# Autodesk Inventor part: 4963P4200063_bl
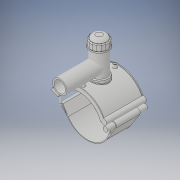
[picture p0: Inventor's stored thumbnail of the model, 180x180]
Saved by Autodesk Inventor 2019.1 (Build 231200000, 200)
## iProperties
Created: 2017-07
Part Number: 4963P4200063_bl
Material: Generic
Document SubType Name: Modeling
Designer: KIM
Density: 1 g/cm^3
Appearance: Default
Author: KIM
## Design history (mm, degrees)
derived "4963P4.ipt"
feature "Solid1::4963P4.ipt" dims "ScaleForDerivedMember" = 10
feature "Solid2::4963P4.ipt" dims "ScaleForDerivedMember" = 10
feature "Solid3::4963P4.ipt" dims "ScaleForDerivedMember" = 10
tag "TaggingFeature1"
body "Solid1"
body "Solid2"
body "Solid3"
other parameters: "d2" = 262.6 [user parameter], "d4" = 176 [user parameter], "d5" = 0 [user parameter], "d6" = 0.1 [user parameter], "d8" = 0 [user parameter], "d19" = 6 [user parameter], "d20" = 6 [user parameter], "d21" = 105.6 [user parameter], "d23" = 0 [user parameter], "d24" = 52.8 [user parameter], "d26" = 0 [user parameter], "d27" = 3 [user parameter], "d28" = 3 [user parameter], "d29" = 3 [user parameter], "d30" = 66.66667 [user parameter], "d31" = 6 [user parameter], "d32" = 0 [user parameter], "d33" = 0 [user parameter], "d34" = 0.6 [user parameter], "d40" = 120.64 [user parameter], "d43" = 0 [user parameter], "d45" = 0 [user parameter], "d47" = 221.6 [user parameter], "d70" = 15 [user parameter], "d72" = 0 [user parameter], "d73" = 6 [user parameter], "d75" = 5 [user parameter], "d76" = 0 [user parameter], "d79" = 15 [user parameter], "d80" = 70.4 [user parameter], "d82" = 5 deg [user parameter], "d84" = 4 [user parameter], "d85" = 14 [user parameter], "d86" = 0 [user parameter], "d87" = 3 [user parameter], "d88" = 0 [user parameter], "d89" = 1 [user parameter], "d90" = 1 [user parameter], "d91" = 140.8 [user parameter], "d92" = 0 [user parameter], "d93" = 0.5 [user parameter], "d94" = 105.26316 [user parameter], "d96" = 236.64 [user parameter], "d97" = 3.52 [user parameter], "d98" = 0 [user parameter], "d102" = 2 [user parameter], "d120" = 140 deg [user parameter], "d121" = 24.228 [user parameter], "d122" = 20 deg [user parameter], "d123" = 464 [user parameter], "d124" = 139.2 [user parameter], "d126" = 0 [user parameter], "d143" = 206 [user parameter], "d145" = 24.61538 [user parameter], "d149" = 3 [user parameter], "d150" = 27.07692 [user parameter], "d153" = 176 [user parameter], "d154" = 0 [user parameter], "d156" = 116 [user parameter], "d157" = 160 deg [user parameter], "d159" = 6.4 [user parameter], "d161" = 3 [user parameter], "d162" = 105.6 [user parameter], "d163" = 0 [user parameter], "d168" = 113.17073 [user parameter], "d170" = 3 [user parameter], "d172" = 0 [user parameter], "d173" = 1 [user parameter], "d176" = 20 deg [user parameter], "d177" = 14 [user parameter], "d178" = 32 [user parameter], "d180" = 0 [user parameter], "d183" = 12.8 [user parameter], "d184" = 11.2 [user parameter], "d185" = 57.2 [user parameter], "d186" = 57.2 [user parameter], "d187" = 116 [user parameter], "d188" = 9.6 [user parameter], "d189" = 14 [user parameter], "d190" = 0 [user parameter], "d191" = 174 [user parameter], "d193" = 6.4 [user parameter], "d194" = 6.16 [user parameter], "d195" = 90 deg [user parameter], "d197" = 0 [user parameter], "d199" = 0 [user parameter], "d200" = 16 [user parameter], "d202" = 0 [user parameter], "d203" = 177 [user parameter], "d204" = 76 [user parameter], "d205" = 56 [user parameter], "d206" = 68 [user parameter], "d207" = 132.75 [user parameter], "d208" = 138.06 [user parameter], "d209" = 164.61 [user parameter], "d210" = 68.8 [user parameter], "d212" = 64 [user parameter], "d213" = 29.25 [user parameter], "d216" = 0 [user parameter], "d219" = 4 [user parameter], "d224" = 0 [user parameter], "d225" = 64 [user parameter], "d226" = 63 [user parameter], "d227" = 50.4 [user parameter], "d228" = 175 [user parameter], "d230" = 4 [user parameter], "B_" = 202 [user parameter], "L_" = 176 [user parameter], "d_t" = 6 [user parameter], "H_2" = 177 [user parameter], "H_1" = 64 [user parameter], "d_1" = 63 [user parameter], "H_" = 175 [user parameter], "d1" = 232 [user parameter], "d148" = 3 [user parameter], "d160" = 3 [user parameter], "d169" = 3 [user parameter], "d192" = 6.4 [user parameter]
